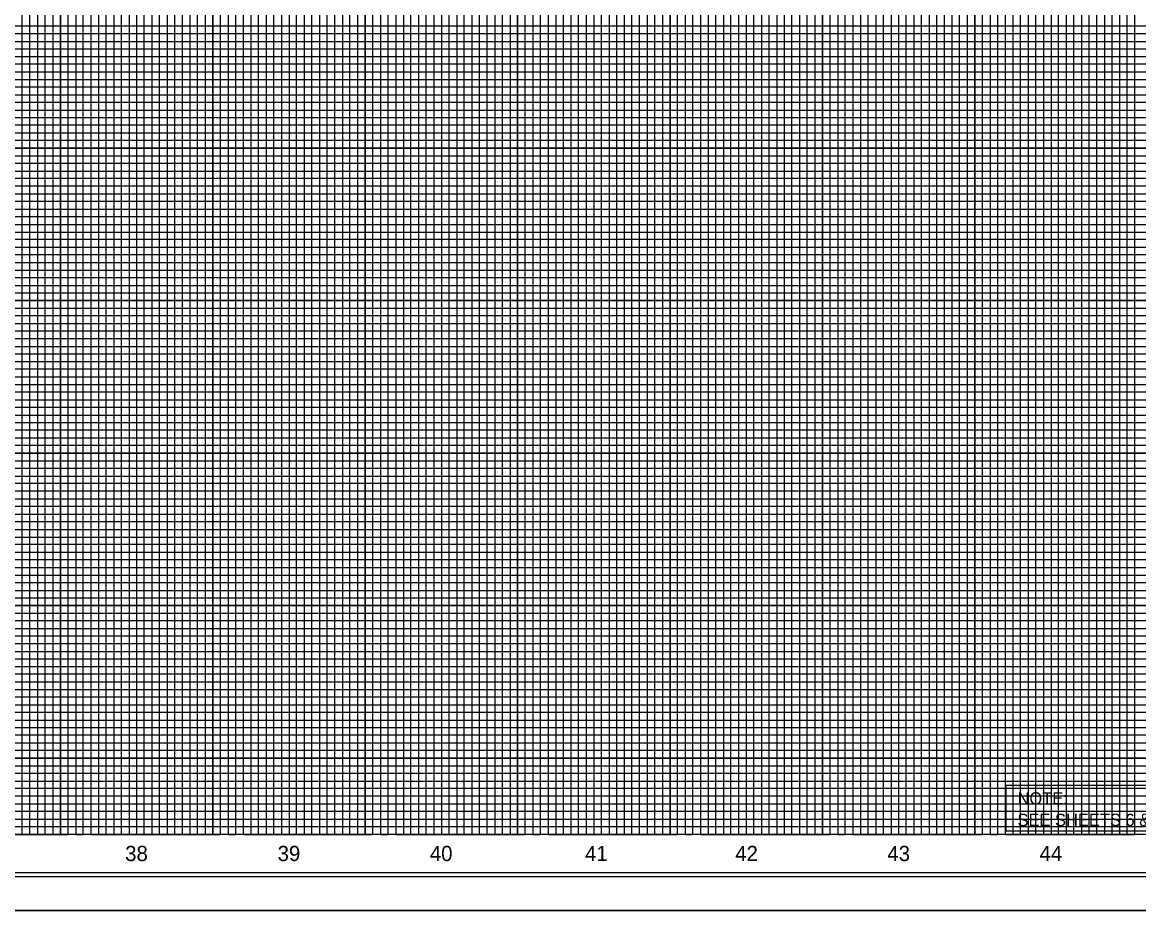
# Model space of a CAD drawing. Extents: x 2195312 to 2197221, y 76953 to 78053.
# Drawn here: x 2196054 to 2196786, y 76953 to 77535 of the extents above; entities that cross this region are included whole.
import ezdxf

# ---------------------------------------------------------------- set-up
doc = ezdxf.new("R2010")
doc.units = 0
for name, color, linetype in [('Exist Structure Minor Culvert Topo', 7, 'Continuous'), ('Old_Level_2', 7, 'Continuous'), ('Old_Level_3', 7, 'Continuous'), ('Prop North Arrow NAD83 for Plan Sheets CELL', 7, 'Continuous'), ('Scratch_Level_0', 7, 'Continuous'), ('Sheet Cutting Line CELL', 7, 'Continuous'), ('Sheet Data Field CELL', 7, 'Continuous'), ('Sheet Plan CELL', 7, 'Continuous'), ('Sheet Plot Border Inside CELL', 7, 'Continuous'), ('Sheet Plot Border Outside CELL', 7, 'Continuous'), ('Sheet Sticker Incomplete CELL', 7, 'Continuous'), ('Sheet Sticker Preliminary CELL', 7, 'Continuous')]:
    doc.layers.add(name, color=color, linetype=linetype)

msp = doc.modelspace()

# ---------------------------------------------------------------- linework, layer by layer
at = {"layer": 'Exist Structure Minor Culvert Topo'}
msp.add_lwpolyline([(2195528.73, 77352.66), (2196928.73, 77352.66), (2196928.73, 77002.66), (2195528.73, 77002.66)], close=True, dxfattribs=at)
at = {"layer": 'Old_Level_2'}
msp.add_lwpolyline([(2196991.23, 78030.21), (2195324.73, 78030.21), (2195324.73, 76975.11), (2196991.23, 76975.11)], close=True, dxfattribs=at)
at = {"layer": 'Old_Level_3'}
msp.add_lwpolyline([(2196699.27, 77034.85), (2196926.09, 77034.85), (2196926.09, 77004.85), (2196699.27, 77004.85)], close=True, dxfattribs=at)
at = {"layer": 'Scratch_Level_0'}
for points in [[(2195311.73, 78052.66), (2196995.73, 78052.66), (2196995.73, 76952.66), (2195311.73, 76952.66)], [(2195528.73, 77702.66), (2196928.73, 77702.66), (2196928.73, 77352.66), (2195528.73, 77352.66)], [(2195528.73, 77702.66), (2196928.73, 77702.66), (2196928.73, 77352.66), (2195528.73, 77352.66)], [(2195528.73, 77402.66), (2196928.73, 77402.66), (2196928.73, 77052.66), (2195528.73, 77052.66)]]:
    msp.add_lwpolyline(points, close=True, dxfattribs=at)
at = {"layer": 'Sheet Cutting Line CELL'}
for points in [[(2196028.73, 77002.66), (2196078.73, 77002.66), (2196078.73, 78027.66)], [(2196128.73, 78027.66), (2196128.73, 77002.66), (2196178.73, 77002.66), (2196178.73, 78027.66)], [(2196228.73, 78027.66), (2196228.73, 77002.66), (2196278.73, 77002.66), (2196278.73, 78027.66)], [(2196328.73, 78027.66), (2196328.73, 77002.66), (2196378.73, 77002.66), (2196378.73, 78027.66)], [(2196428.73, 78027.66), (2196428.73, 77002.66), (2196478.73, 77002.66), (2196478.73, 78027.66)], [(2196528.73, 78027.66), (2196528.73, 77002.66), (2196578.73, 77002.66), (2196578.73, 78027.66)], [(2196628.73, 78027.66), (2196628.73, 77002.66), (2196678.73, 77002.66), (2196678.73, 78027.66)], [(2196728.73, 78027.66), (2196728.73, 77002.66), (2196778.73, 77002.66), (2196778.73, 78027.66)], [(2196978.73, 77452.66), (2195478.73, 77452.66), (2195478.73, 77502.66), (2196978.73, 77502.66)], [(2196978.73, 77352.66), (2195478.73, 77352.66), (2195478.73, 77402.66), (2196978.73, 77402.66)], [(2196978.73, 77252.66), (2195478.73, 77252.66), (2195478.73, 77302.66), (2196978.73, 77302.66)], [(2196978.73, 77152.66), (2195478.73, 77152.66), (2195478.73, 77202.66), (2196978.73, 77202.66)], [(2196978.73, 77052.66), (2195478.73, 77052.66), (2195478.73, 77102.66), (2196978.73, 77102.66)]]:
    msp.add_lwpolyline(points, dxfattribs=at)
at = {"layer": 'Sheet Data Field CELL'}
for points in [[(2196058.73, 77002.66), (2196058.73, 78027.66)], [(2196063.73, 78027.66), (2196063.73, 77002.66), (2196068.73, 77002.66), (2196068.73, 78027.66)], [(2196073.73, 78027.66), (2196073.73, 77002.66), (2196083.73, 77002.66), (2196083.73, 78027.66)], [(2196088.73, 78027.66), (2196088.73, 77002.66), (2196088.73, 77002.66), (2196093.73, 77002.66), (2196093.73, 78027.66)], [(2196098.73, 78027.66), (2196098.73, 77002.66), (2196108.73, 77002.66), (2196108.73, 78027.66)], [(2196113.73, 78027.66), (2196113.73, 77002.66), (2196118.73, 77002.66), (2196118.73, 78027.66)], [(2196123.73, 78027.66), (2196123.73, 77002.66), (2196133.73, 77002.66), (2196133.73, 78027.66)], [(2196138.73, 78027.66), (2196138.73, 77002.66), (2196143.73, 77002.66), (2196143.73, 78027.66)], [(2196148.73, 78027.66), (2196148.73, 77002.66), (2196158.73, 77002.66), (2196158.73, 78027.66)], [(2196163.73, 78027.66), (2196163.73, 77002.66), (2196168.73, 77002.66), (2196168.73, 78027.66)], [(2196173.73, 78027.66), (2196173.73, 77002.66), (2196183.73, 77002.66), (2196183.73, 78027.66)], [(2196188.73, 78027.66), (2196188.73, 77002.66), (2196193.73, 77002.66), (2196193.73, 78027.66)], [(2196198.73, 78027.66), (2196198.73, 77002.66), (2196208.73, 77002.66), (2196208.73, 78027.66)], [(2196213.73, 78027.66), (2196213.73, 77002.66), (2196218.73, 77002.66), (2196218.73, 78027.66)], [(2196223.73, 78027.66), (2196223.73, 77002.66), (2196233.73, 77002.66), (2196233.73, 78027.66)], [(2196238.73, 78027.66), (2196238.73, 77002.66)], [(2196238.73, 77002.66), (2196243.73, 77002.66), (2196243.73, 78027.06)], [(2196248.73, 78027.06), (2196248.73, 77002.66), (2196258.73, 77002.66), (2196258.73, 78027.66)], [(2196263.73, 78027.66), (2196263.73, 77002.66), (2196268.73, 77002.66), (2196268.73, 78027.66)], [(2196273.73, 78027.66), (2196273.73, 77002.66), (2196283.73, 77002.66), (2196283.73, 78027.66)], [(2196288.73, 78027.66), (2196288.73, 77002.66), (2196293.73, 77002.66), (2196293.73, 78027.66)], [(2196298.73, 78027.66), (2196298.73, 77002.66), (2196308.73, 77002.66), (2196308.73, 78027.66)], [(2196313.73, 78027.66), (2196313.73, 77002.66), (2196318.73, 77002.66), (2196318.73, 78027.66)], [(2196323.73, 78027.66), (2196323.73, 77002.66), (2196333.73, 77002.66), (2196333.73, 78027.66)], [(2196338.73, 78027.66), (2196338.73, 77002.66), (2196343.73, 77002.66), (2196343.73, 78027.66)], [(2196348.73, 78027.66), (2196348.73, 77002.66), (2196358.73, 77002.66), (2196358.73, 78027.66)], [(2196363.73, 78027.66), (2196363.73, 77002.66), (2196368.73, 77002.66), (2196368.73, 78027.66)], [(2196373.73, 78027.66), (2196373.73, 77002.66), (2196383.73, 77002.66), (2196383.73, 78027.66)], [(2196388.73, 78027.66), (2196388.73, 77002.66), (2196393.73, 77002.66), (2196393.73, 78027.66)], [(2196398.73, 78027.66), (2196398.73, 77002.66), (2196408.73, 77002.66), (2196408.73, 78027.66)], [(2196413.73, 78027.66), (2196413.73, 77002.66), (2196418.73, 77002.66), (2196418.73, 78027.66)], [(2196423.73, 78027.66), (2196423.73, 77002.66), (2196433.73, 77002.66), (2196433.73, 78027.66)], [(2196438.73, 78027.66), (2196438.73, 77002.66), (2196443.73, 77002.66), (2196443.73, 78027.66)], [(2196448.73, 78027.66), (2196448.73, 77002.66), (2196458.73, 77002.66), (2196458.73, 78027.66)], [(2196463.73, 78027.66), (2196463.73, 77002.66), (2196468.73, 77002.66), (2196468.73, 78027.66)], [(2196473.73, 78027.66), (2196473.73, 77002.66), (2196483.73, 77002.66), (2196483.73, 78027.66)], [(2196488.73, 78027.66), (2196488.73, 77002.66), (2196493.73, 77002.66), (2196493.73, 78027.66)], [(2196498.73, 78027.66), (2196498.73, 77002.66), (2196508.73, 77002.66), (2196508.73, 78027.66)], [(2196513.73, 78027.66), (2196513.73, 77002.66), (2196518.73, 77002.66), (2196518.73, 78027.66)], [(2196523.73, 78027.66), (2196523.73, 77002.66), (2196533.73, 77002.66), (2196533.73, 78027.66)], [(2196538.73, 78027.66), (2196538.73, 77002.66), (2196543.73, 77002.66), (2196543.73, 78027.66)], [(2196548.73, 78027.66), (2196548.73, 77002.66)], [(2196548.73, 77002.66), (2196558.73, 77002.66), (2196558.73, 78027.66)], [(2196563.73, 78027.66), (2196563.73, 77002.66), (2196568.73, 77002.66), (2196568.73, 78027.66)], [(2196573.73, 78027.66), (2196573.73, 77002.66), (2196583.73, 77002.66), (2196583.73, 78027.66)], [(2196588.73, 78027.66), (2196588.73, 77002.66), (2196593.73, 77002.66), (2196593.73, 78027.66)], [(2196598.73, 78027.66), (2196598.73, 77002.66), (2196608.73, 77002.66), (2196608.73, 78027.66)], [(2196613.73, 78027.66), (2196613.73, 77002.66), (2196618.73, 77002.66), (2196618.73, 78027.66)], [(2196623.73, 78027.66), (2196623.73, 77002.66), (2196633.73, 77002.66), (2196633.73, 78027.66)], [(2196638.73, 78027.66), (2196638.73, 77002.66), (2196643.73, 77002.66), (2196643.73, 78027.66)], [(2196648.73, 78027.66), (2196648.73, 77002.66), (2196658.73, 77002.66), (2196658.73, 78027.66)], [(2196663.73, 78027.66), (2196663.73, 77002.66), (2196668.73, 77002.66), (2196668.73, 78027.66)], [(2196673.73, 78027.66), (2196673.73, 77002.66), (2196683.73, 77002.66), (2196683.73, 78027.66)], [(2196688.73, 78027.66), (2196688.73, 77002.66), (2196693.73, 77002.66), (2196693.73, 78027.66)], [(2196698.73, 78027.66), (2196698.73, 77002.66), (2196708.73, 77002.66), (2196708.73, 78027.66)], [(2196713.73, 78027.66), (2196713.73, 77002.66), (2196718.73, 77002.66), (2196718.73, 78027.66)], [(2196723.73, 78027.66), (2196723.73, 77002.66), (2196733.73, 77002.66), (2196733.73, 78027.66)], [(2196738.73, 78027.66), (2196738.73, 77002.66), (2196743.73, 77002.66), (2196743.73, 78027.66)], [(2196748.73, 78027.66), (2196748.73, 77002.66), (2196758.73, 77002.66), (2196758.73, 78027.66)], [(2196763.73, 78027.66), (2196763.73, 77002.66), (2196768.73, 77002.66), (2196768.73, 78027.66)], [(2196773.73, 78027.66), (2196773.73, 77002.66), (2196783.73, 77002.66), (2196783.73, 77866.61)], [(2196928.73, 77532.66), (2195528.73, 77532.66), (2195528.73, 77522.66), (2196928.73, 77522.66)], [(2196928.73, 77517.66), (2195528.73, 77517.66), (2195528.73, 77512.66), (2196928.73, 77512.66)], [(2196928.73, 77507.66), (2195528.73, 77507.66)], [(2195528.73, 77497.66), (2196928.73, 77497.66)], [(2196928.73, 77492.66), (2195528.73, 77492.66), (2195528.73, 77487.66), (2196928.73, 77487.66)], [(2196928.73, 77482.66), (2195528.73, 77482.66), (2195528.73, 77472.66), (2196928.73, 77472.66)], [(2196928.73, 77467.66), (2195528.73, 77467.66), (2195528.73, 77462.66), (2196928.73, 77462.66)], [(2196928.73, 77457.66), (2195528.73, 77457.66), (2195528.73, 77447.66), (2196928.73, 77447.66)], [(2196928.73, 77442.66), (2195528.73, 77442.66), (2195528.73, 77437.66), (2196928.73, 77437.66)], [(2196928.73, 77432.66), (2195528.73, 77432.66), (2195528.73, 77422.66), (2196928.73, 77422.66)], [(2196928.73, 77417.66), (2195528.73, 77417.66), (2195528.73, 77412.66), (2196928.73, 77412.66)], [(2196928.73, 77407.66), (2195528.73, 77407.66), (2195528.73, 77397.66), (2196928.73, 77397.66)], [(2196928.73, 77392.66), (2195528.73, 77392.66), (2195528.73, 77387.66), (2196928.73, 77387.66)], [(2196928.73, 77382.66), (2195528.73, 77382.66), (2195528.73, 77372.66), (2196928.73, 77372.66)], [(2196928.73, 77367.66), (2195528.73, 77367.66), (2195528.73, 77362.66), (2196928.73, 77362.66)], [(2196928.73, 77357.66), (2195528.73, 77357.66), (2195528.73, 77347.66), (2196928.73, 77347.66)], [(2196928.73, 77342.66), (2195528.73, 77342.66), (2195528.73, 77337.66), (2196928.73, 77337.66)], [(2196928.73, 77332.66), (2195528.73, 77332.66), (2195528.73, 77322.66), (2196928.73, 77322.66)], [(2196928.73, 77317.66), (2195528.73, 77317.66), (2195528.73, 77312.66), (2196928.73, 77312.66)], [(2196928.73, 77307.66), (2195528.73, 77307.66), (2195528.73, 77297.66), (2196928.73, 77297.66)], [(2196928.73, 77292.66), (2195528.73, 77292.66), (2195528.73, 77287.66), (2196928.73, 77287.66)], [(2196928.73, 77282.66), (2195528.73, 77282.66), (2195528.73, 77272.66), (2196928.73, 77272.66)], [(2196928.73, 77267.66), (2195528.73, 77267.66), (2195528.73, 77262.66), (2196928.73, 77262.66)], [(2196928.73, 77257.66), (2195528.73, 77257.66), (2195528.73, 77247.66), (2196928.73, 77247.66)], [(2196928.73, 77242.66), (2195528.73, 77242.66), (2195528.73, 77237.66), (2196928.73, 77237.66)], [(2196928.73, 77232.66), (2195528.73, 77232.66), (2195528.73, 77222.66), (2196928.73, 77222.66)], [(2196928.73, 77217.66), (2195528.73, 77217.66), (2195528.73, 77212.66), (2196928.73, 77212.66)], [(2196928.73, 77207.66), (2195528.73, 77207.66)], [(2195528.73, 77197.66), (2196928.73, 77197.66)], [(2196928.73, 77192.66), (2195528.73, 77192.66), (2195528.73, 77187.66), (2196928.73, 77187.66)], [(2196928.73, 77182.66), (2195528.73, 77182.66)], [(2195528.73, 77172.66), (2196928.73, 77172.66)], [(2196928.73, 77167.66), (2195528.73, 77167.66), (2195528.73, 77162.66), (2196928.73, 77162.66)], [(2196928.73, 77157.66), (2195528.73, 77157.66), (2195528.73, 77147.66), (2196928.73, 77147.66)], [(2196928.73, 77142.66), (2195528.73, 77142.66), (2195528.73, 77137.66), (2196928.73, 77137.66)], [(2196928.73, 77132.66), (2195528.73, 77132.66), (2195528.73, 77122.66), (2196928.73, 77122.66)], [(2196928.73, 77117.66), (2195528.73, 77117.66), (2195528.73, 77112.66), (2196928.73, 77112.66)], [(2196928.73, 77107.66), (2195528.73, 77107.66), (2195528.73, 77097.66), (2196928.73, 77097.66)], [(2196928.73, 77092.66), (2195528.73, 77092.66), (2195528.73, 77087.66), (2196928.73, 77087.66)], [(2196928.73, 77082.66), (2195528.73, 77082.66), (2195528.73, 77072.66), (2196928.73, 77072.66)], [(2196928.73, 77067.66), (2195528.73, 77067.66), (2195528.73, 77062.66), (2196928.73, 77062.66)], [(2196928.73, 77057.66), (2195528.73, 77057.66), (2195528.73, 77047.66), (2196928.73, 77047.66)], [(2196928.73, 77042.66), (2195528.73, 77042.66), (2195528.73, 77037.66), (2196928.73, 77037.66)], [(2196928.73, 77032.66), (2195528.73, 77032.66), (2195528.73, 77022.66), (2196928.73, 77022.66)], [(2196928.73, 77017.66), (2195528.73, 77017.66), (2195528.73, 77012.66), (2196928.73, 77012.66)], [(2196928.73, 77007.66), (2195528.73, 77007.66)]]:
    msp.add_lwpolyline(points, dxfattribs=at)
at = {"layer": 'Sheet Plan CELL'}
msp.add_lwpolyline([(2196995.73, 78052.66), (2195311.73, 78052.66), (2195311.73, 76952.66), (2196995.73, 76952.66)], close=True, dxfattribs=at)
at = {"layer": 'Sheet Plot Border Inside CELL'}
for p, q in [((2195478.73, 77352.66), (2196978.73, 77352.66)), ((2196978.73, 77002.66), (2195478.73, 77002.66))]:
    msp.add_line(p, q, dxfattribs=at)
msp.add_lwpolyline([(2196978.73, 78027.66), (2195478.73, 78027.66), (2195478.73, 76977.66), (2196978.73, 76977.66)], close=True, dxfattribs=at)
at = {"layer": 'Sheet Plot Border Outside CELL'}
for points in [[(2196003.73, 77002.66), (2196053.73, 77002.66), (2196053.73, 78027.66)], [(2196103.73, 78027.66), (2196103.73, 77002.66), (2196153.73, 77002.66), (2196153.73, 78027.66)], [(2196203.73, 78027.66), (2196203.73, 77002.66), (2196253.73, 77002.66), (2196253.73, 78027.66)], [(2196303.73, 78027.66), (2196303.73, 77002.66), (2196353.73, 77002.66), (2196353.73, 78027.66)], [(2196403.73, 78027.66), (2196403.73, 77002.66), (2196453.73, 77002.66), (2196453.73, 78027.66)], [(2196503.73, 78027.66), (2196503.73, 77002.66), (2196553.73, 77002.66), (2196553.73, 78027.66)], [(2196603.73, 78027.66), (2196603.73, 77002.66), (2196653.73, 77002.66), (2196653.73, 78027.66)], [(2196703.73, 78027.66), (2196703.73, 77002.66), (2196753.73, 77002.66), (2196753.73, 78027.66)], [(2196978.73, 77527.66), (2195478.73, 77527.66), (2195478.73, 77477.66), (2196978.73, 77477.66)], [(2196978.73, 77427.66), (2195478.73, 77427.66), (2195478.73, 77377.66), (2196978.73, 77377.66)], [(2196978.73, 77327.66), (2195478.73, 77327.66), (2195478.73, 77277.66), (2196978.73, 77277.66)], [(2196978.73, 77227.66), (2195478.73, 77227.66), (2195478.73, 77177.66), (2196978.73, 77177.66)], [(2196978.73, 77127.66), (2195478.73, 77127.66), (2195478.73, 77077.66), (2196978.73, 77077.66)], [(2196978.73, 77027.66), (2195478.73, 77027.66)]]:
    msp.add_lwpolyline(points, dxfattribs=at)
at = {"layer": 'Sheet Sticker Incomplete CELL'}
msp.add_line((2195311.73, 76952.66), (2196995.73, 76952.66), dxfattribs=at)
at = {"layer": 'Sheet Sticker Preliminary CELL'}
for p, q in [((2196078.73, 78027.66), (2196078.73, 77002.66)), ((2196128.73, 78027.66), (2196128.73, 77002.66)), ((2196178.73, 78027.66), (2196178.73, 77002.66)), ((2196228.73, 78027.66), (2196228.73, 77002.66)), ((2196278.73, 78027.66), (2196278.73, 77002.66)), ((2196328.73, 78027.66), (2196328.73, 77002.66)), ((2196378.73, 78027.66), (2196378.73, 77002.66)), ((2196428.73, 78027.66), (2196428.73, 77002.66)), ((2196478.73, 78027.66), (2196478.73, 77002.66)), ((2196528.73, 78027.66), (2196528.73, 77002.66)), ((2196578.73, 78027.66), (2196578.73, 77002.66)), ((2196628.73, 78027.66), (2196628.73, 77002.66)), ((2196678.73, 78027.66), (2196678.73, 77002.66)), ((2196728.73, 78027.66), (2196728.73, 77002.66)), ((2196778.73, 77002.66), (2196778.73, 77890.11)), ((2195478.73, 77502.66), (2196978.73, 77502.66)), ((2195478.73, 77452.66), (2196978.73, 77452.66)), ((2195478.73, 77402.66), (2196978.73, 77402.66)), ((2195478.73, 77352.66), (2196978.73, 77352.66)), ((2195478.73, 77302.66), (2196978.73, 77302.66)), ((2195478.73, 77252.66), (2196978.73, 77252.66)), ((2195478.73, 77202.66), (2196978.73, 77202.66)), ((2195478.73, 77152.66), (2196978.73, 77152.66)), ((2195478.73, 77102.66), (2196978.73, 77102.66)), ((2195478.73, 77052.66), (2196978.73, 77052.66))]:
    msp.add_line(p, q, dxfattribs=at)

# ---------------------------------------------------------------- texts
at = {"layer": 'Exist Structure Minor Culvert Topo'}
for s, height, p in [('NOTE:', 8.077, (2196706.72, 77022.27)), ('SEE SHEETS 6 & 7 FOR -L1- PLAN', 8.0769, (2196706.73, 77008.13))]:
    msp.add_text(s, height=height, rotation=0.02303, dxfattribs=at).set_placement(p)
at = {"layer": 'Prop North Arrow NAD83 for Plan Sheets CELL'}
for s, p in [('38', (2196121.2, 76985.16)), ('39', (2196221.24, 76985.16)), ('40', (2196321.12, 76985.16)), ('41', (2196422.95, 76985.16)), ('42', (2196521.5, 76985.16)), ('43', (2196621.34, 76985.16)), ('44', (2196721.18, 76985.16))]:
    msp.add_text(s, height=10, dxfattribs=at).set_placement(p)

doc.saveas('drawing.dxf')
